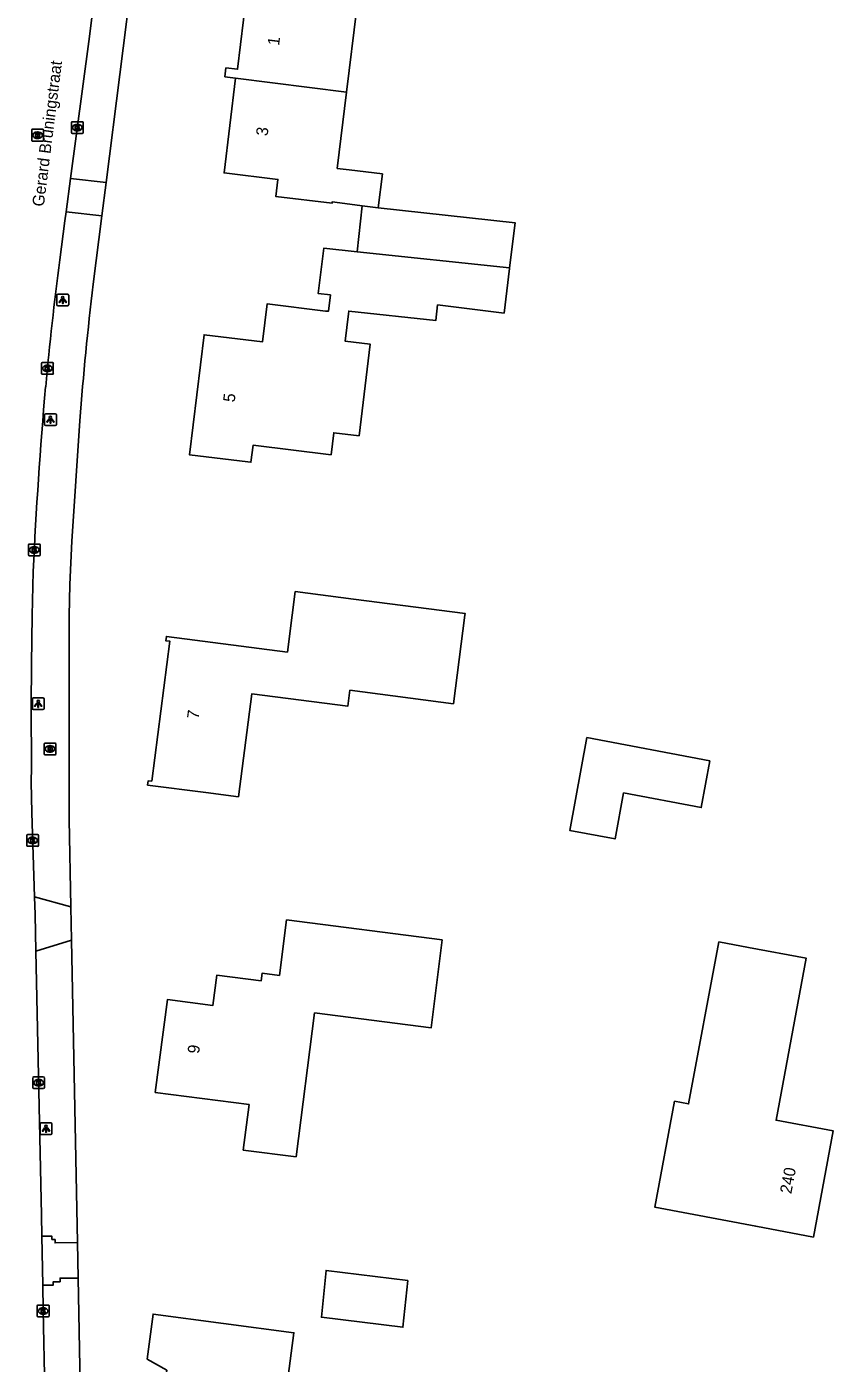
# Model space of a CAD drawing. Extents: x 161258 to 161838, y 380836 to 381727.
# Drawn here: x 161656.2 to 161724.9, y 381186.3 to 381300.1 of the extents above; entities that cross this region are included whole.
import ezdxf

# ---------------------------------------------------------------- set-up
doc = ezdxf.new("R2010")
doc.units = 0
for name, color, linetype in [('IMGEO_Brandkraan', 7, 'Continuous'), ('IMGEO_Kolk', 7, 'Continuous'), ('IMGEO_Lichtpunt', 7, 'Continuous'), ('IMGEO_Muur', 7, 'Continuous'), ('IMGEO_Openbare_ruimte_label', 7, 'Continuous'), ('IMGEO_Pand', 7, 'Continuous'), ('IMGEO_Pand_nummerreeks', 7, 'Continuous'), ('IMGEO_Rijbaan_lokaal_open', 7, 'Continuous'), ('IMGEO_Rioolput', 7, 'Continuous'), ('IMGEO_Voetpad_open', 7, 'Continuous')]:
    doc.layers.add(name, color=color, linetype=linetype)

msp = doc.modelspace()

# ---------------------------------------------------------------- linework, layer by layer
at = {"layer": 'IMGEO_Brandkraan'}
for p, q in [((161657.72, 381238.19), (161657.72, 381239.04)), ((161657.8, 381239.12), (161658.65, 381239.12)), ((161658.72, 381239.04), (161658.72, 381238.19)), ((161658.65, 381238.12), (161657.8, 381238.12)), ((161658.21, 381238.9), (161658.24, 381238.9)), ((161658.23, 381238.34), (161658.21, 381238.34))]:
    msp.add_line(p, q, dxfattribs=at)
for points in [[(161657.72, 381238.19), (161657.72, 381239.04)], [(161657.8, 381239.12), (161658.65, 381239.12)], [(161658.72, 381239.04), (161658.72, 381238.19)], [(161658.65, 381238.12), (161657.8, 381238.12)], [(161658.07, 381238.82), (161658.07, 381238.42), (161658.28, 381238.42)], [(161658.3, 381238.82), (161658.07, 381238.82)], [(161658.25, 381238.74), (161658.2, 381238.74), (161658.2, 381238.66)], [(161658.2, 381238.66), (161658.25, 381238.66)], [(161658.26, 381238.58), (161658.2, 381238.58), (161658.2, 381238.5)], [(161658.2, 381238.5), (161658.26, 381238.5)]]:
    msp.add_lwpolyline(points, dxfattribs=at)
for centre, radius, start, end in [((161657.8, 381239.04), 0.0765, 91.552, 178.448), ((161657.8, 381239.04), 0.0765, 91.552, 178.448), ((161658.65, 381239.04), 0.0765, 1.552, 88.448), ((161658.65, 381239.04), 0.0765, 1.552, 88.448), ((161657.8, 381238.19), 0.0765, 181.552, 268.448), ((161657.8, 381238.19), 0.0765, 181.552, 268.448), ((161658.25, 381238.7), 0.0379, 267.8285, 90.9355), ((161658.26, 381238.54), 0.0404, 269.8759, 90.5077), ((161658.29, 381238.67), 0.251, 268.6676, 293.5347), ((161658.31, 381238.67), 0.145, 59.4692, 91.5367), ((161658.33, 381238.72), 0.0922, 285.5137, 58.1501), ((161658.34, 381238.53), 0.105, 301.3115, 78.989), ((161658.65, 381238.19), 0.0765, 271.552, 358.448), ((161658.65, 381238.19), 0.0765, 271.552, 358.448)]:
    msp.add_arc(centre, radius, start, end, dxfattribs=at)
for centre, major_axis, ratio, start_param, end_param in [((161658.21, 381238.62), (-0.387, 0.002), 0.722429, 4.712389, 7.853982), ((161658.23, 381238.62), (-0.39, 0.002), 0.717154, 1.570796, 4.712389)]:
    msp.add_ellipse(centre, major_axis=major_axis, ratio=ratio, start_param=start_param, end_param=end_param, dxfattribs=at)
at = {"layer": 'IMGEO_Kolk'}
for p, q in [((161660.05, 381291.11), (161660.05, 381291.97)), ((161660.12, 381292.04), (161660.97, 381292.04)), ((161660.54, 381291.82), (161660.56, 381291.82)), ((161661.05, 381291.97), (161661.05, 381291.11)), ((161660.97, 381291.04), (161660.12, 381291.04)), ((161660.56, 381291.26), (161660.53, 381291.26)), ((161657.5, 381270.6), (161657.5, 381271.45)), ((161657.58, 381271.53), (161658.43, 381271.53)), ((161657.99, 381271.31), (161658.02, 381271.31)), ((161658.5, 381271.45), (161658.5, 381270.6)), ((161658.43, 381270.53), (161657.58, 381270.53)), ((161658.01, 381270.75), (161657.99, 381270.75)), ((161656.46, 381256.07), (161657.31, 381256.07)), ((161656.39, 381255.14), (161656.39, 381255.99)), ((161657.31, 381255.07), (161656.46, 381255.07)), ((161656.9, 381255.29), (161656.87, 381255.29)), ((161656.88, 381255.85), (161656.9, 381255.85)), ((161657.39, 381255.99), (161657.39, 381255.14)), ((161656.24, 381230.4), (161656.24, 381231.25)), ((161656.31, 381231.33), (161657.17, 381231.33)), ((161656.73, 381231.11), (161656.75, 381231.11)), ((161657.24, 381231.25), (161657.24, 381230.4)), ((161657.17, 381230.33), (161656.31, 381230.33)), ((161656.75, 381230.55), (161656.73, 381230.55)), ((161656.76, 381209.76), (161656.76, 381210.62)), ((161656.83, 381210.69), (161657.68, 381210.69)), ((161657.76, 381210.62), (161657.76, 381209.76)), ((161657.68, 381209.69), (161656.83, 381209.69)), ((161657.24, 381210.47), (161657.27, 381210.47)), ((161657.27, 381209.91), (161657.24, 381209.91)), ((161657.14, 381190.33), (161657.14, 381191.18)), ((161657.21, 381191.25), (161658.07, 381191.25)), ((161658.14, 381191.18), (161658.14, 381190.33)), ((161658.07, 381190.25), (161657.21, 381190.25)), ((161657.65, 381190.47), (161657.62, 381190.47)), ((161657.63, 381191.03), (161657.65, 381191.03))]:
    msp.add_line(p, q, dxfattribs=at)
for points in [[(161660.05, 381291.11), (161660.05, 381291.97)], [(161660.12, 381292.04), (161660.97, 381292.04)], [(161660.37, 381291.74), (161660.49, 381291.74), (161660.49, 381291.59), (161660.62, 381291.74), (161660.79, 381291.74), (161660.64, 381291.59), (161660.79, 381291.34), (161660.64, 381291.34), (161660.56, 381291.5), (161660.49, 381291.44), (161660.49, 381291.34), (161660.37, 381291.34), (161660.37, 381291.74)], [(161661.05, 381291.97), (161661.05, 381291.11)], [(161660.97, 381291.04), (161660.12, 381291.04)], [(161657.5, 381270.6), (161657.5, 381271.45)], [(161657.58, 381271.53), (161658.43, 381271.53)], [(161657.82, 381271.23), (161657.95, 381271.23), (161657.95, 381271.08), (161658.08, 381271.23), (161658.24, 381271.23), (161658.09, 381271.08), (161658.25, 381270.83), (161658.09, 381270.83), (161658.01, 381270.99), (161657.95, 381270.92), (161657.95, 381270.83), (161657.82, 381270.83), (161657.82, 381271.23)], [(161658.5, 381271.45), (161658.5, 381270.6)], [(161658.43, 381270.53), (161657.58, 381270.53)], [(161656.46, 381256.07), (161657.31, 381256.07)], [(161656.39, 381255.14), (161656.39, 381255.99)], [(161657.31, 381255.07), (161656.46, 381255.07)], [(161656.71, 381255.77), (161656.83, 381255.77), (161656.83, 381255.62), (161656.96, 381255.77), (161657.13, 381255.77), (161656.98, 381255.62), (161657.13, 381255.37), (161656.98, 381255.37), (161656.9, 381255.53), (161656.83, 381255.47), (161656.83, 381255.37), (161656.71, 381255.37), (161656.71, 381255.77)], [(161657.39, 381255.99), (161657.39, 381255.14)], [(161656.24, 381230.4), (161656.24, 381231.25)], [(161656.31, 381231.33), (161657.17, 381231.33)], [(161656.56, 381231.03), (161656.68, 381231.03), (161656.68, 381230.88), (161656.81, 381231.03), (161656.98, 381231.03), (161656.83, 381230.88), (161656.98, 381230.63), (161656.83, 381230.63), (161656.75, 381230.79), (161656.68, 381230.73), (161656.68, 381230.63), (161656.56, 381230.63), (161656.56, 381231.03)], [(161657.24, 381231.25), (161657.24, 381230.4)], [(161657.17, 381230.33), (161656.31, 381230.33)], [(161656.76, 381209.76), (161656.76, 381210.62)], [(161656.83, 381210.69), (161657.68, 381210.69)], [(161657.76, 381210.62), (161657.76, 381209.76)], [(161657.68, 381209.69), (161656.83, 381209.69)], [(161657.08, 381210.39), (161657.2, 381210.39), (161657.2, 381210.24), (161657.33, 381210.39), (161657.49, 381210.39), (161657.35, 381210.24), (161657.5, 381209.99), (161657.35, 381209.99), (161657.26, 381210.16), (161657.2, 381210.09), (161657.2, 381209.99), (161657.08, 381209.99), (161657.08, 381210.39)], [(161657.14, 381190.33), (161657.14, 381191.18)], [(161657.21, 381191.25), (161658.07, 381191.25)], [(161658.14, 381191.18), (161658.14, 381190.33)], [(161658.07, 381190.25), (161657.21, 381190.25)], [(161657.46, 381190.95), (161657.58, 381190.95), (161657.58, 381190.8), (161657.71, 381190.95), (161657.88, 381190.95), (161657.73, 381190.8), (161657.88, 381190.55), (161657.73, 381190.55), (161657.65, 381190.72), (161657.58, 381190.65), (161657.58, 381190.55), (161657.46, 381190.55), (161657.46, 381190.95)]]:
    msp.add_lwpolyline(points, dxfattribs=at)
for centre, start, end in [((161660.12, 381291.96), 91.552, 178.448), ((161660.12, 381291.96), 91.552, 178.448), ((161660.97, 381291.96), 1.552, 88.448), ((161660.97, 381291.96), 1.552, 88.448), ((161660.12, 381291.11), 181.552, 268.448), ((161660.12, 381291.11), 181.552, 268.448), ((161660.97, 381291.11), 271.552, 358.448), ((161660.97, 381291.11), 271.552, 358.448), ((161657.58, 381271.45), 91.552, 178.448), ((161657.58, 381271.45), 91.552, 178.448), ((161658.43, 381271.45), 1.552, 88.448), ((161658.43, 381271.45), 1.552, 88.448), ((161657.58, 381270.6), 181.552, 268.448), ((161657.58, 381270.6), 181.552, 268.448), ((161658.43, 381270.6), 271.552, 358.448), ((161658.43, 381270.6), 271.552, 358.448), ((161656.46, 381255.99), 91.552, 178.448), ((161656.46, 381255.99), 91.552, 178.448), ((161657.31, 381255.99), 1.552, 88.448), ((161657.31, 381255.99), 1.552, 88.448), ((161656.46, 381255.14), 181.552, 268.448), ((161656.46, 381255.14), 181.552, 268.448), ((161657.31, 381255.14), 271.552, 358.448), ((161657.31, 381255.14), 271.552, 358.448), ((161656.32, 381231.25), 91.552, 178.448), ((161656.32, 381231.25), 91.552, 178.448), ((161657.16, 381231.25), 1.552, 88.448), ((161657.16, 381231.25), 1.552, 88.448), ((161656.32, 381230.4), 181.552, 268.448), ((161656.32, 381230.4), 181.552, 268.448), ((161657.16, 381230.4), 271.552, 358.448), ((161657.16, 381230.4), 271.552, 358.448), ((161656.83, 381210.62), 91.552, 178.448), ((161656.83, 381210.62), 91.552, 178.448), ((161657.68, 381210.62), 1.552, 88.448), ((161657.68, 381210.62), 1.552, 88.448), ((161656.83, 381209.77), 181.552, 268.448), ((161656.83, 381209.77), 181.552, 268.448), ((161657.68, 381209.77), 271.552, 358.448), ((161657.68, 381209.77), 271.552, 358.448), ((161657.21, 381191.18), 91.552, 178.448), ((161657.21, 381191.18), 91.552, 178.448), ((161658.06, 381191.18), 1.552, 88.448), ((161658.06, 381191.18), 1.552, 88.448), ((161657.21, 381190.33), 181.552, 268.448), ((161657.21, 381190.33), 181.552, 268.448), ((161658.06, 381190.33), 271.552, 358.448), ((161658.06, 381190.33), 271.552, 358.448)]:
    msp.add_arc(centre, 0.0765, start, end, dxfattribs=at)
for centre, major_axis, ratio, start_param, end_param in [((161660.53, 381291.54), (-0.387, 0.002), 0.722429, 4.712389, 7.853982), ((161660.56, 381291.54), (-0.39, 0.002), 0.717154, 1.570796, 4.712389), ((161657.99, 381271.03), (-0.387, 0.002), 0.722429, 4.712389, 7.853982), ((161658.01, 381271.03), (-0.39, 0.002), 0.717154, 1.570796, 4.712389), ((161656.87, 381255.57), (-0.387, 0.002), 0.722429, 4.712389, 7.853982), ((161656.9, 381255.57), (-0.39, 0.002), 0.717154, 1.570796, 4.712389), ((161656.73, 381230.83), (-0.387, 0.002), 0.722429, 4.712389, 7.853982), ((161656.75, 381230.83), (-0.39, 0.002), 0.717154, 1.570796, 4.712389), ((161657.24, 381210.19), (-0.387, 0.002), 0.722429, 4.712389, 7.853982), ((161657.27, 381210.19), (-0.39, 0.002), 0.717154, 1.570796, 4.712389), ((161657.63, 381190.75), (-0.387, 0.002), 0.722429, 4.712389, 7.853982), ((161657.65, 381190.75), (-0.39, 0.002), 0.717154, 1.570796, 4.712389)]:
    msp.add_ellipse(centre, major_axis=major_axis, ratio=ratio, start_param=start_param, end_param=end_param, dxfattribs=at)
at = {"layer": 'IMGEO_Lichtpunt'}
for p, q in [((161658.81, 381277.26), (161658.81, 381276.45)), ((161658.81, 381277.26), (161658.81, 381276.45)), ((161659.71, 381277.36), (161658.91, 381277.36)), ((161659.71, 381277.36), (161658.91, 381277.36)), ((161659.81, 381276.45), (161659.81, 381277.26)), ((161659.81, 381276.45), (161659.81, 381277.26)), ((161658.91, 381276.36), (161659.71, 381276.36)), ((161658.91, 381276.36), (161659.71, 381276.36)), ((161657.76, 381267.06), (161657.76, 381266.26)), ((161657.76, 381267.06), (161657.76, 381266.26)), ((161658.67, 381267.16), (161657.86, 381267.16)), ((161658.67, 381267.16), (161657.86, 381267.16)), ((161658.76, 381266.26), (161658.76, 381267.06)), ((161658.76, 381266.26), (161658.76, 381267.06)), ((161657.86, 381266.16), (161658.67, 381266.16)), ((161657.86, 381266.16), (161658.67, 381266.16)), ((161656.72, 381242.87), (161656.72, 381242.06)), ((161656.72, 381242.87), (161656.72, 381242.06)), ((161657.62, 381242.96), (161656.81, 381242.96)), ((161657.62, 381242.96), (161656.81, 381242.96)), ((161657.71, 381242.06), (161657.71, 381242.87)), ((161657.71, 381242.06), (161657.71, 381242.87)), ((161656.81, 381241.97), (161657.62, 381241.97)), ((161656.81, 381241.97), (161657.62, 381241.97)), ((161657.39, 381206.68), (161657.39, 381205.87)), ((161657.39, 381206.68), (161657.39, 381205.87)), ((161658.29, 381206.77), (161657.48, 381206.77)), ((161658.29, 381206.77), (161657.48, 381206.77)), ((161658.38, 381205.87), (161658.38, 381206.68)), ((161658.38, 381205.87), (161658.38, 381206.68)), ((161657.48, 381205.78), (161658.29, 381205.78)), ((161657.48, 381205.78), (161658.29, 381205.78))]:
    msp.add_line(p, q, dxfattribs=at)
for points in [[(161659.19, 381276.92), (161659.22, 381276.9), (161659.04, 381276.63), (161659, 381276.66), (161659.19, 381276.92)], [(161659.29, 381276.88), (161659.33, 381276.88), (161659.33, 381276.55), (161659.29, 381276.55), (161659.29, 381276.88)], [(161659.4, 381276.9), (161659.44, 381276.92), (161659.62, 381276.66), (161659.58, 381276.63), (161659.4, 381276.9)], [(161658.14, 381266.73), (161658.18, 381266.7), (161657.99, 381266.44), (161657.95, 381266.47), (161658.14, 381266.73)], [(161658.24, 381266.68), (161658.29, 381266.68), (161658.29, 381266.36), (161658.24, 381266.36), (161658.24, 381266.68)], [(161658.35, 381266.7), (161658.39, 381266.73), (161658.57, 381266.46), (161658.54, 381266.44), (161658.35, 381266.7)], [(161657.09, 381242.53), (161657.13, 381242.51), (161656.94, 381242.24), (161656.9, 381242.27), (161657.09, 381242.53)], [(161657.19, 381242.49), (161657.24, 381242.49), (161657.24, 381242.16), (161657.19, 381242.16), (161657.19, 381242.49)], [(161657.3, 381242.51), (161657.34, 381242.53), (161657.53, 381242.27), (161657.49, 381242.24), (161657.3, 381242.51)], [(161657.76, 381206.34), (161657.8, 381206.31), (161657.61, 381206.05), (161657.57, 381206.08), (161657.76, 381206.34)], [(161657.86, 381206.29), (161657.91, 381206.29), (161657.91, 381205.97), (161657.86, 381205.97), (161657.86, 381206.29)], [(161657.97, 381206.31), (161658.01, 381206.34), (161658.2, 381206.08), (161658.16, 381206.05), (161657.97, 381206.31)]]:
    msp.add_lwpolyline(points, dxfattribs=at)
for centre in [(161659.31, 381277.06), (161658.26, 381266.86), (161657.22, 381242.67), (161657.89, 381206.48)]:
    msp.add_circle(centre, 0.0994, dxfattribs=at)
for centre, start, end in [((161658.91, 381277.26), 90, 180), ((161658.91, 381277.26), 90, 180), ((161659.71, 381277.26), 0, 90), ((161659.71, 381277.26), 0, 90), ((161658.91, 381276.45), 180, 270), ((161658.91, 381276.45), 180, 270), ((161659.71, 381276.45), 270, 0), ((161659.71, 381276.45), 270, 360), ((161657.86, 381267.06), 90, 180), ((161657.86, 381267.06), 90, 180), ((161658.67, 381267.06), 0, 90), ((161658.67, 381267.06), 0, 90), ((161657.86, 381266.26), 180, 270), ((161657.86, 381266.26), 180, 270), ((161658.67, 381266.26), 270, 0), ((161658.67, 381266.26), 270, 360), ((161656.81, 381242.87), 90, 180), ((161656.81, 381242.87), 90, 180), ((161657.62, 381242.87), 0, 90), ((161657.62, 381242.87), 0, 90), ((161656.81, 381242.06), 180, 270), ((161656.81, 381242.06), 180, 270), ((161657.62, 381242.06), 270, 0), ((161657.62, 381242.06), 270, 360), ((161657.48, 381206.68), 90, 180), ((161657.48, 381206.68), 90, 180), ((161658.29, 381206.68), 0, 90), ((161658.29, 381206.68), 0, 90), ((161657.48, 381205.87), 180, 270), ((161657.48, 381205.87), 180, 270), ((161658.29, 381205.87), 270, 0), ((161658.29, 381205.87), 270, 360)]:
    msp.add_arc(centre, 0.0946, start, end, dxfattribs=at)
at = {"layer": 'IMGEO_Muur'}
msp.add_lwpolyline([(161660.07, 381256.32), (161660.76, 381266.57)], dxfattribs=at)
at = {"layer": 'IMGEO_Pand'}
for points in [[(161674.02, 381295.74), (161673.11, 381295.86), (161673.2, 381296.62), (161674.19, 381296.5), (161674.96, 381302.85), (161679.98, 381302.23), (161684.34, 381301.7), (161683.47, 381294.55)], [(161684.81, 381284.88), (161683.33, 381285.07), (161682.24, 381285.2), (161682.23, 381285.1), (161677.44, 381285.68), (161677.62, 381287.12), (161673.04, 381287.68), (161674.02, 381295.74)], [(161683.47, 381294.55), (161674.02, 381295.74)], [(161683.47, 381294.55), (161682.67, 381288.06), (161683.69, 381287.94), (161686.52, 381287.59), (161686.17, 381284.71)], [(161684.38, 381280.95), (161684.81, 381284.88)], [(161684.81, 381284.88), (161686.17, 381284.71)], [(161686.17, 381284.71), (161697.82, 381283.43), (161697.35, 381279.58)], [(161697.35, 381279.58), (161697.34, 381279.54), (161696.88, 381275.74), (161691.22, 381276.44), (161691.06, 381275.1), (161683.65, 381275.91), (161683.62, 381275.68), (161683.34, 381273.35), (161685.48, 381273.08), (161684.53, 381265.29), (161682.38, 381265.55), (161682.15, 381263.67), (161675.51, 381264.48), (161675.33, 381263.03), (161675.05, 381263.06), (161670.09, 381263.67), (161671.34, 381273.89), (161676.31, 381273.29), (161676.7, 381276.52), (161681.67, 381275.91), (161681.92, 381275.89), (161682.09, 381277.29), (161681.05, 381277.42), (161681.52, 381281.26), (161684.38, 381280.95)], [(161697.35, 381279.58), (161684.38, 381280.95)], [(161692.57, 381242.47), (161683.75, 381243.61), (161683.57, 381242.25), (161675.39, 381243.31), (161674.26, 381234.54), (161671.49, 381234.9), (161666.53, 381235.54), (161666.58, 381235.91), (161666.89, 381235.88), (161668.43, 381247.79), (161668.08, 381247.83), (161668.13, 381248.2), (161678.43, 381246.87), (161678.84, 381250), (161679.1, 381252.02), (161684.06, 381251.38), (161693.56, 381250.16), (161693.54, 381250), (161692.57, 381242.47)], [(161714.41, 381237.6), (161713.67, 381233.63), (161707.06, 381234.87), (161706.33, 381230.96), (161702.47, 381231.68), (161703.93, 381239.58), (161714.41, 381237.6)], [(161691.62, 381222.35), (161690.66, 381214.86), (161680.75, 381216.14), (161679.17, 381203.88), (161674.67, 381204.46), (161675.17, 381208.33), (161667.18, 381209.36), (161668.21, 381217.27), (161672.09, 381216.77), (161672.43, 381219.36), (161676.2, 381218.88), (161676.28, 381219.52), (161677.75, 381219.33), (161678.36, 381224.06), (161691.62, 381222.35)], [(161715.17, 381222.19), (161717.69, 381221.71), (161722.61, 381220.79), (161720.03, 381206.99), (161724.9, 381206.08), (161723.22, 381197.05), (161718.3, 381197.97), (161709.72, 381199.58), (161711.4, 381208.61), (161712.59, 381208.39), (161715.17, 381222.19)], [(161688.68, 381193.34), (161688.27, 381189.36), (161681.33, 381190.22), (161681.73, 381194.2), (161688.68, 381193.34)], [(161675.9, 381174.85), (161669.27, 381175.7), (161669.33, 381176.12), (161666.98, 381176.42), (161668.18, 381185.7), (161666.5, 381186.65), (161667, 381190.48), (161678.99, 381188.9), (161678.45, 381184.77), (161675.89, 381185.1), (161674.86, 381177.12), (161676.08, 381176.2), (161675.9, 381174.85)]]:
    msp.add_lwpolyline(points, dxfattribs=at)
at = {"layer": 'IMGEO_Rijbaan_lokaal_open'}
for points in [[(161659.96, 381287.2), (161661.54, 381298.88), (161662.39, 381305.65)], [(161659.59, 381284.37), (161659.96, 381287.2)], [(161659.07, 381280.28), (161659.49, 381283.59), (161659.59, 381284.37)], [(161656.9, 381226.01), (161656.66, 381233.17), (161656.63, 381235.81), (161656.64, 381237.03), (161656.63, 381242.22), (161656.65, 381245.83), (161656.71, 381249.98), (161656.8, 381253.73)], [(161657.02, 381221.39), (161656.95, 381224.53), (161656.9, 381226.01)], [(161657.53, 381197.13), (161657.5, 381198.9), (161657.02, 381221.39)], [(161657.6, 381192.94), (161657.53, 381197.13)], [(161657.94, 381178.47), (161657.88, 381179.14), (161657.78, 381183.88), (161657.64, 381190.82), (161657.6, 381192.94)]]:
    msp.add_lwpolyline(points, dxfattribs=at)
for centre, radius, start, end in [((161928.86, 381244.55), 272.15, 172.4567, 174.7465), ((162012.92, 381237.78), 356.48, 174.9002, 177.4349)]:
    msp.add_arc(centre, radius, start, end, dxfattribs=at)
at = {"layer": 'IMGEO_Rioolput'}
for p, q in [((161656.74, 381291.39), (161657.59, 381291.39)), ((161656.67, 381290.47), (161656.67, 381291.32)), ((161657.59, 381290.39), (161656.74, 381290.39)), ((161657.15, 381291.17), (161657.18, 381291.17)), ((161657.18, 381290.61), (161657.15, 381290.61)), ((161657.67, 381291.32), (161657.67, 381290.47))]:
    msp.add_line(p, q, dxfattribs=at)
for points in [[(161656.74, 381291.39), (161657.59, 381291.39)], [(161656.67, 381290.47), (161656.67, 381291.32)], [(161657.59, 381290.39), (161656.74, 381290.39)], [(161657.25, 381291.09), (161657, 381291.09), (161657, 381290.69)], [(161657, 381290.69), (161657.13, 381290.69), (161657.13, 381290.86), (161657.14, 381290.86)], [(161657.18, 381291.01), (161657.13, 381291.01), (161657.13, 381290.93)], [(161657.13, 381290.93), (161657.18, 381290.93)], [(161657.18, 381290.83), (161657.26, 381290.69), (161657.39, 381290.69), (161657.33, 381290.82)], [(161657.67, 381291.32), (161657.67, 381290.47)]]:
    msp.add_lwpolyline(points, dxfattribs=at)
for centre, radius, start, end in [((161656.74, 381291.32), 0.0765, 91.552, 178.448), ((161656.74, 381291.32), 0.0765, 91.552, 178.448), ((161657.59, 381291.32), 0.0765, 1.552, 88.448), ((161657.59, 381291.32), 0.0765, 1.552, 88.448), ((161656.74, 381290.47), 0.0765, 181.552, 268.448), ((161656.74, 381290.47), 0.0765, 181.552, 268.448), ((161657.14, 381290.8), 0.0533, 26.0293, 88.6989), ((161657.19, 381290.92), 0.0964, 77.0061, 93.1865), ((161657.16, 381291.12), 0.19, 274.7715, 282.9687), ((161657.2, 381290.97), 0.0378, 276.6634, 79.6772), ((161657.25, 381290.98), 0.109, 350.3612, 89.416), ((161657.25, 381290.98), 0.112, 277.5842, 350.9817), ((161657.24, 381290.77), 0.108, 29.5134, 73.7905), ((161657.59, 381290.47), 0.0765, 271.552, 358.448), ((161657.59, 381290.47), 0.0765, 271.552, 358.448)]:
    msp.add_arc(centre, radius, start, end, dxfattribs=at)
for centre, major_axis, ratio, start_param, end_param in [((161657.15, 381290.89), (-0.387, 0.002), 0.722429, 4.712389, 7.853982), ((161657.18, 381290.89), (-0.39, 0.002), 0.717154, 1.570796, 4.712389)]:
    msp.add_ellipse(centre, major_axis=major_axis, ratio=ratio, start_param=start_param, end_param=end_param, dxfattribs=at)
at = {"layer": 'IMGEO_Voetpad_open'}
for points in [[(161665.33, 381305.29), (161663, 381286.85)], [(161659.96, 381287.2), (161663, 381286.85)], [(161663, 381286.85), (161662.64, 381284.01)], [(161659.59, 381284.37), (161662.64, 381284.01)], [(161662.64, 381284.01), (161661.9, 381278.2)], [(161660.76, 381266.57), (161660.07, 381256.32), (161659.92, 381252.62), (161659.85, 381249.96), (161659.86, 381232.62), (161660, 381225.18)], [(161660, 381225.18), (161656.9, 381226.01)], [(161660, 381225.18), (161660.06, 381222.33)], [(161660.06, 381222.33), (161657.02, 381221.39)], [(161660.56, 381196.58), (161660.06, 381222.33)], [(161657.53, 381197.13), (161658.37, 381197.13), (161658.39, 381196.84), (161658.66, 381196.83), (161658.66, 381196.55), (161660.56, 381196.58)], [(161660.62, 381193.54), (161660.56, 381196.58)], [(161657.6, 381192.94), (161658.49, 381192.94), (161658.49, 381193.23), (161659.08, 381193.24), (161659.08, 381193.55), (161660.62, 381193.54)], [(161665.62, 381169.31), (161664.36, 381170.6), (161663.26, 381172.03), (161662, 381174.21), (161661.51, 381175.7), (161661.21, 381177.25), (161660.8, 381184.49), (161660.62, 381193.54)]]:
    msp.add_lwpolyline(points, dxfattribs=at)
msp.add_arc((161940.54, 381244.93), 280.62, 173.1924, 175.5778, dxfattribs=at)

# ---------------------------------------------------------------- texts
at = {"layer": 'IMGEO_Openbare_ruimte_label'}
msp.add_text('Gerard Bruningstraat', height=1, rotation=82.8181, dxfattribs=at).set_placement((161657.69, 381284.77))
at = {"layer": 'IMGEO_Pand_nummerreeks'}
for s, rotation, p in [('1', 82.7686, (161677.72, 381298.48)), ('3', 82.7686, (161676.74, 381290.78)), ('5', 83.026, (161673.94, 381268.11)), ('7', 82.6484, (161670.87, 381241.13)), ('9', 82.6492, (161670.91, 381212.62)), ('240', 79.426, (161721.33, 381200.68))]:
    msp.add_text(s, height=1, rotation=rotation, dxfattribs=at).set_placement(p)

doc.saveas('drawing.dxf')
